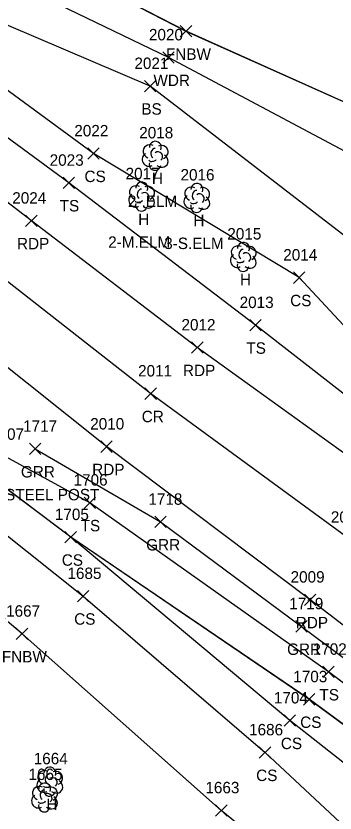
# Model space of a CAD drawing. Extents: x 1415642 to 1422021, y 544543 to 547232.
# Drawn here: x 1415966.4 to 1416022.2, y 546878.2 to 547017.8 of the extents above; entities that cross this region are included whole.
import ezdxf

# ---------------------------------------------------------------- set-up
doc = ezdxf.new("R2010")
doc.units = 0
for name, color, linetype in [('L_A', 7, 'Continuous'), ('L_C', 7, 'Continuous'), ('L_I', 7, 'Continuous'), ('L_TIC', 7, 'Continuous'), ('LAWA', 7, 'Continuous'), ('LELB', 7, 'Continuous'), ('LFNC', 7, 'Continuous'), ('LTD', 7, 'Continuous'), ('P_A', 7, 'Continuous'), ('P_I', 7, 'Continuous'), ('P_TIC', 7, 'Continuous'), ('PET', 7, 'Continuous'), ('PRC', 7, 'Continuous'), ('R_A', 7, 'Continuous'), ('R_C', 7, 'Continuous'), ('R_I', 7, 'Continuous'), ('R_TIC', 7, 'Continuous'), ('RGR', 7, 'Continuous')]:
    doc.layers.add(name, color=color, linetype=linetype)

msp = doc.modelspace()

# ---------------------------------------------------------------- linework, layer by layer
at = {"layer": 'L_TIC'}
for points in [[(1415995.11, 547014.1), (1415997.11, 547016.1)], [(1415997.11, 547014.1), (1415995.11, 547016.1)], [(1415992.05, 547009.51), (1415994.05, 547011.51)], [(1415994.05, 547009.51), (1415992.05, 547011.51)], [(1415988.85, 547004.5), (1415990.85, 547006.5)], [(1415990.85, 547004.5), (1415988.85, 547006.5)], [(1415978.91, 546992.7), (1415980.91, 546994.7)], [(1415980.91, 546992.7), (1415978.91, 546994.7)], [(1415974.6, 546987.56), (1415976.6, 546989.56)], [(1415976.6, 546987.56), (1415974.6, 546989.56)], [(1416014.88, 546970.97), (1416016.88, 546972.97)], [(1416016.88, 546970.97), (1416014.88, 546972.97)], [(1416007.25, 546962.65), (1416009.25, 546964.65)], [(1416009.25, 546962.65), (1416007.25, 546964.65)], [(1415978.27, 546931.57), (1415980.27, 546933.57)], [(1415980.27, 546931.57), (1415978.27, 546933.57)], [(1415974.94, 546925.54), (1415976.94, 546927.54)], [(1415976.94, 546925.54), (1415974.94, 546927.54)], [(1415974.94, 546925.54), (1415976.94, 546927.54)], [(1415976.94, 546925.54), (1415974.94, 546927.54)], [(1415977.11, 546915.22), (1415979.11, 546917.22)], [(1415979.11, 546915.22), (1415977.11, 546917.22)], [(1415966.43, 546908.62), (1415968.43, 546910.62)], [(1415968.43, 546908.62), (1415966.43, 546910.62)], [(1416020.03, 546901.96), (1416022.03, 546903.96)], [(1416022.03, 546901.96), (1416020.03, 546903.96)], [(1416016.63, 546897.15), (1416018.63, 546899.15)], [(1416018.63, 546897.15), (1416016.63, 546899.15)], [(1416013.25, 546893.44), (1416015.25, 546895.44)], [(1416015.25, 546893.44), (1416013.25, 546895.44)], [(1416008.92, 546887.85), (1416010.92, 546889.85)], [(1416010.92, 546887.85), (1416008.92, 546889.85)], [(1416001.28, 546877.71), (1416003.28, 546879.71)], [(1416003.28, 546877.71), (1416001.28, 546879.71)]]:
    msp.add_lwpolyline(points, dxfattribs=at)
at = {"layer": 'LAWA'}
for points in [[(1416240.56, 546960.73), (1416233.2, 546953.27), (1416224.51, 546941.93), (1416214.85, 546929.39), (1416199.95, 546923.14), (1416193.46, 546920.24), (1416179.13, 546920.7), (1416159.93, 546927.15), (1416126.32, 546945.38), (1416100.02, 546952.8), (1416028.43, 546991.66), (1415993.05, 547010.51), (1415954.88, 547028.97)], [(1416240.56, 546960.73), (1416233.2, 546953.27), (1416224.51, 546941.93), (1416214.86, 546929.39), (1416199.95, 546923.14), (1416193.46, 546920.24), (1416179.13, 546920.7), (1416159.93, 546927.15), (1416126.32, 546945.39), (1416100.02, 546952.81), (1416028.43, 546991.66), (1415993.05, 547010.51), (1415954.88, 547028.96)]]:
    msp.add_lwpolyline(points, dxfattribs=at)
at = {"layer": 'LELB'}
for points in [[(1416091.47, 546896.23), (1416067.28, 546915.33), (1416036.7, 546941.48), (1416008.25, 546963.65), (1415975.6, 546988.56), (1415942.26, 547013.09), (1415909.12, 547036.86), (1415872.92, 547061.56), (1415845.5, 547087.74), (1415809.03, 547112.5), (1415805.73, 547114.89), (1415787.7, 547125.97), (1415788.24, 547129.84), (1415790.68, 547131.85)], [(1416091.47, 546896.23), (1416067.28, 546915.33), (1416036.71, 546941.48), (1416008.26, 546963.65), (1415975.6, 546988.56), (1415942.26, 547013.09), (1415909.12, 547036.86), (1415872.92, 547061.56), (1415845.5, 547087.74), (1415809.04, 547112.5), (1415805.73, 547114.9), (1415787.7, 547125.97), (1415788.24, 547129.84), (1415790.68, 547131.85)], [(1416166.26, 546865.71), (1416159.51, 546874.18), (1416128.86, 546893.05), (1416099.94, 546911.95), (1416080.11, 546927.17), (1416051.61, 546951.27), (1416024.79, 546978.54), (1415989.85, 547005.5), (1415949.92, 547022.61), (1415918.77, 547047.8), (1415880.24, 547071.02), (1415848.8, 547092.4)], [(1416166.26, 546865.71), (1416159.51, 546874.18), (1416128.86, 546893.05), (1416099.95, 546911.94), (1416080.11, 546927.17), (1416051.61, 546951.27), (1416024.79, 546978.54), (1415989.85, 547005.5), (1415949.92, 547022.61), (1415918.78, 547047.8), (1415880.25, 547071.01), (1415848.8, 547092.4)], [(1416210.45, 546810.14), (1416187.24, 546828.5), (1416172.35, 546839.03), (1416162.91, 546845.64), (1416145.69, 546861.76), (1416125.16, 546875.54), (1416093.4, 546901.43), (1416075.19, 546919.9), (1416045.66, 546942.32), (1416039.77, 546946.29), (1416015.88, 546971.97), (1415979.91, 546993.7), (1415946.5, 547018.2), (1415914.22, 547042.27), (1415877.25, 547066.68), (1415845.5, 547087.74)], [(1416210.45, 546810.14), (1416187.24, 546828.5), (1416172.36, 546839.03), (1416162.91, 546845.64), (1416145.7, 546861.76), (1416125.16, 546875.54), (1416093.4, 546901.44), (1416075.18, 546919.9), (1416045.66, 546942.32), (1416039.77, 546946.29), (1416015.88, 546971.97), (1415979.91, 546993.7), (1415946.51, 547018.2), (1415914.22, 547042.27), (1415877.24, 547066.68), (1415845.5, 547087.74)], [(1416200.69, 546756.25), (1416177.76, 546767.63), (1416166.72, 546775.57), (1416158.94, 546780.74), (1416149.8, 546790.95), (1416145.27, 546792.19), (1416135.47, 546803.24), (1416119.09, 546819.38), (1416087.86, 546845.73), (1416058.66, 546867.92), (1416017.63, 546898.15), (1415975.94, 546926.54), (1415961.59, 546937.35), (1415930.25, 546967.22), (1415904.85, 546987.6), (1415883.27, 547005.7), (1415850.56, 547030.99), (1415821.69, 547055.02)], [(1416200.69, 546756.25), (1416177.77, 546767.63), (1416166.72, 546775.57), (1416158.93, 546780.74), (1416149.8, 546790.95), (1416145.28, 546792.19), (1416135.47, 546803.24), (1416119.09, 546819.38), (1416087.87, 546845.73), (1416058.67, 546867.92), (1416017.63, 546898.16), (1415975.95, 546926.55), (1415961.6, 546937.34), (1415930.25, 546967.22), (1415904.86, 546987.6), (1415883.28, 547005.7), (1415850.57, 547030.99), (1415821.7, 547055.02)], [(1415881.61, 546996.31), (1415913.06, 546969.47), (1415944.07, 546943.36), (1415978.11, 546916.22), (1416009.92, 546888.85), (1416034.36, 546866.02), (1416055.92, 546848.02), (1416074.4, 546832.78), (1416094.73, 546817.39), (1416113.97, 546812.22), (1416083.13, 546840.22), (1416056.24, 546861.43), (1416014.25, 546894.44), (1415975.94, 546926.54)], [(1415881.62, 546996.31), (1415913.07, 546969.47), (1415944.08, 546943.36), (1415978.12, 546916.23), (1416009.93, 546888.84), (1416034.36, 546866.03), (1416055.93, 546848.02), (1416074.4, 546832.78), (1416094.74, 546817.39), (1416113.98, 546812.22), (1416083.14, 546840.22), (1416056.24, 546861.43), (1416014.25, 546894.43), (1415975.95, 546926.55)], [(1416413.88, 546519.84), (1416385.73, 546558.12), (1416356.85, 546595.36), (1416336.82, 546621.39), (1416300.66, 546661.66), (1416278.22, 546684.25), (1416249.88, 546714.04), (1416230.93, 546728.9), (1416221.86, 546737.5), (1416200.69, 546756.25), (1416176.24, 546778.44), (1416157.26, 546793.38), (1416140.02, 546808.9), (1416121.84, 546825.58), (1416090.2, 546848.7), (1416061.67, 546872.28), (1416021.03, 546902.96), (1415979.27, 546932.57), (1415964.6, 546940.59)], [(1416413.88, 546519.84), (1416385.73, 546558.12), (1416356.85, 546595.36), (1416336.82, 546621.39), (1416300.66, 546661.66), (1416278.22, 546684.25), (1416249.88, 546714.04), (1416230.93, 546728.9), (1416221.87, 546737.51), (1416200.69, 546756.25), (1416176.24, 546778.44), (1416157.26, 546793.38), (1416140.03, 546808.9), (1416121.84, 546825.58), (1416090.21, 546848.7), (1416061.68, 546872.28), (1416021.04, 546902.96), (1415979.28, 546932.57), (1415964.61, 546940.59)]]:
    msp.add_lwpolyline(points, dxfattribs=at)
at = {"layer": 'LFNC'}
for points in [[(1416067.58, 546984.06), (1416031.2, 546999.34), (1415996.11, 547015.1), (1415957.45, 547035.03), (1415922.34, 547052.78), (1415883.85, 547076.17), (1415852.09, 547094.57), (1415823.18, 547113.63), (1415819.4, 547116.14), (1415815.46, 547118.48), (1415790.83, 547135.32)], [(1416067.58, 546984.06), (1416031.2, 546999.34), (1415996.12, 547015.09), (1415957.45, 547035.03), (1415922.34, 547052.78), (1415883.85, 547076.17), (1415852.09, 547094.57), (1415823.18, 547113.64), (1415819.41, 547116.14), (1415815.45, 547118.48), (1415790.83, 547135.32)], [(1416115.75, 546796.75), (1416105.56, 546801.9), (1416090.13, 546811.78), (1416082.81, 546817.76), (1416078.29, 546817.48), (1416069.09, 546824.45), (1416051.15, 546839.14), (1416026.27, 546859.13), (1416002.28, 546878.71), (1415967.43, 546909.62), (1415937.82, 546934.52), (1415909.35, 546961.09), (1415874.55, 546995.04)], [(1416115.75, 546796.75), (1416105.57, 546801.9), (1416090.14, 546811.78), (1416082.82, 546817.76), (1416078.29, 546817.48), (1416069.1, 546824.45), (1416051.16, 546839.14), (1416026.28, 546859.13), (1416002.28, 546878.71), (1415967.43, 546909.62), (1415937.83, 546934.51), (1415909.36, 546961.09), (1415874.56, 546995.04)]]:
    msp.add_lwpolyline(points, dxfattribs=at)
at = {"layer": 'LTD'}
for p, q in [((1415990.69, 546993.35), (1415990.69, 546993.35)), ((1415990.69, 546993.35), (1415990.69, 546993.35)), ((1415988.32, 546986.2), (1415988.32, 546986.2)), ((1415988.32, 546986.2), (1415988.32, 546986.2)), ((1415997.97, 546985.98), (1415997.97, 546985.98)), ((1415997.97, 546985.98), (1415997.97, 546985.98)), ((1416006.1, 546975.65), (1416006.1, 546975.65)), ((1416006.1, 546975.65), (1416006.1, 546975.65)), ((1415972.26, 546883.79), (1415972.26, 546883.79)), ((1415972.26, 546883.79), (1415972.26, 546883.79)), ((1415971.35, 546881.03), (1415971.35, 546881.03)), ((1415971.35, 546881.03), (1415971.35, 546881.03))]:
    msp.add_line(p, q, dxfattribs=at)
for centre in [(1415990.74, 546994.79), (1415988.36, 546987.64), (1415998.02, 546987.41), (1416006.14, 546977.09), (1415972.3, 546885.23), (1415971.39, 546882.46)]:
    msp.add_arc(centre, 1.05, 335.5272, 180.9563, dxfattribs=at)
for centre, major_axis, ratio, start_param, end_param in [((1415989.9, 546994.02), (1.21, -0.51), 0.895232, 1.570796, 4.712389), ((1415991.74, 546993.93), (-1.14, -0.48), 0.949671, 1.570796, 4.712389), ((1415990.49, 546993.81), (-0.208, -0.792), 0.645439, 3.141593, 6.283185), ((1415991.19, 546993.18), (-0.5, 0.667), 0.989748, 3.141593, 6.283185), ((1415989.61, 546992.64), (0.58, -1.04), 0.959034, 3.141593, 6.283185), ((1415990.24, 546992.6), (-0.625, -0.083), 0.423636, 0, 3.141593), ((1415991.69, 546992.52), (-1.09, 0.79), 0.841452, 1.570796, 4.712389), ((1415990.69, 546991.85), (0.26, 1.06), 0.942809, 1.570796, 4.712389), ((1415987.52, 546986.87), (1.21, -0.51), 0.895232, 1.570796, 4.712389), ((1415988.11, 546986.66), (-0.208, -0.792), 0.645439, 3.141593, 6.283185), ((1415988.82, 546986.04), (-0.5, 0.667), 0.989748, 3.141593, 6.283185), ((1415989.36, 546986.79), (-1.14, -0.48), 0.949671, 1.570796, 4.712389), ((1415997.18, 546986.64), (1.21, -0.51), 0.895232, 1.570796, 4.712389), ((1415997.76, 546986.43), (-0.208, -0.792), 0.645439, 3.141593, 6.283185), ((1415999.01, 546986.56), (-1.14, -0.48), 0.949671, 1.570796, 4.712389), ((1415987.23, 546985.5), (0.58, -1.04), 0.959034, 3.141593, 6.283185), ((1415987.86, 546985.45), (-0.625, -0.083), 0.423636, 0, 3.141593), ((1415989.32, 546985.37), (-1.09, 0.79), 0.841452, 1.570796, 4.712389), ((1415996.89, 546985.27), (0.58, -1.04), 0.959034, 3.141593, 6.283185), ((1415998.47, 546985.81), (-0.5, 0.667), 0.989748, 3.141593, 6.283185), ((1415998.97, 546985.14), (-1.09, 0.79), 0.841452, 1.570796, 4.712389), ((1415988.32, 546984.7), (0.26, 1.06), 0.942809, 1.570796, 4.712389), ((1415997.97, 546984.48), (0.26, 1.06), 0.942809, 1.570796, 4.712389), ((1415997.51, 546985.22), (-0.625, -0.083), 0.423636, 0, 3.141593), ((1416005.31, 546976.32), (1.21, -0.51), 0.895232, 1.570796, 4.712389), ((1416007.14, 546976.24), (-1.14, -0.48), 0.949671, 1.570796, 4.712389), ((1416005.01, 546974.94), (0.58, -1.04), 0.959034, 3.141593, 6.283185), ((1416005.89, 546976.11), (-0.208, -0.792), 0.645439, 3.141593, 6.283185), ((1416006.6, 546975.49), (-0.5, 0.667), 0.989748, 3.141593, 6.283185), ((1416007.1, 546974.82), (-1.09, 0.79), 0.841452, 1.570796, 4.712389), ((1416006.1, 546974.15), (0.26, 1.06), 0.942809, 1.570796, 4.712389), ((1416005.64, 546974.9), (-0.625, -0.083), 0.423636, 0, 3.141593), ((1415971.46, 546884.46), (1.21, -0.51), 0.895232, 1.570796, 4.712389), ((1415972.05, 546884.25), (-0.208, -0.792), 0.645439, 3.141593, 6.283185), ((1415973.3, 546884.37), (-1.14, -0.48), 0.949671, 1.570796, 4.712389), ((1415971.17, 546883.08), (0.58, -1.04), 0.959034, 3.141593, 6.283185), ((1415972.76, 546883.62), (-0.5, 0.667), 0.989748, 3.141593, 6.283185), ((1415973.26, 546882.96), (-1.09, 0.79), 0.841452, 1.570796, 4.712389), ((1415970.56, 546881.69), (1.21, -0.51), 0.895232, 1.570796, 4.712389), ((1415971.14, 546881.48), (-0.208, -0.792), 0.645439, 3.141593, 6.283185), ((1415972.26, 546882.29), (0.26, 1.06), 0.942809, 1.570796, 4.712389), ((1415971.8, 546883.04), (-0.625, -0.083), 0.423636, 0, 3.141593), ((1415972.39, 546881.61), (-1.14, -0.48), 0.949671, 1.570796, 4.712389), ((1415970.26, 546880.32), (0.58, -1.04), 0.959034, 3.141593, 6.283185), ((1415971.85, 546880.86), (-0.5, 0.667), 0.989748, 3.141593, 6.283185), ((1415972.35, 546880.19), (-1.09, 0.79), 0.841452, 1.570796, 4.712389), ((1415971.35, 546879.53), (0.26, 1.06), 0.942809, 1.570796, 4.712389), ((1415970.89, 546880.28), (-0.625, -0.083), 0.423636, 0, 3.141593)]:
    msp.add_ellipse(centre, major_axis=major_axis, ratio=ratio, start_param=start_param, end_param=end_param, dxfattribs=at)
at = {"layer": 'P_TIC'}
for points in [[(1415968.06, 546980.93), (1415970.06, 546982.93)], [(1415970.06, 546980.93), (1415968.06, 546982.93)], [(1415997.08, 546958.73), (1415999.08, 546960.73)], [(1415999.08, 546958.73), (1415997.08, 546960.73)], [(1415988.92, 546950.67), (1415990.92, 546952.67)], [(1415990.92, 546950.67), (1415988.92, 546952.67)], [(1415981.21, 546941.39), (1415983.21, 546943.39)], [(1415983.21, 546941.39), (1415981.21, 546943.39)], [(1416016.81, 546914.59), (1416018.81, 546916.59)], [(1416018.81, 546914.59), (1416016.81, 546916.59)]]:
    msp.add_lwpolyline(points, dxfattribs=at)
at = {"layer": 'PET'}
for points in [[(1416435.56, 546537.44), (1416408.53, 546574.61), (1416379.54, 546611.97), (1416358.62, 546637.86), (1416320.38, 546681.18), (1416299.04, 546704.62), (1416270.68, 546734.26), (1416256.1, 546749.21), (1416221.42, 546781.44), (1416197.8, 546803.68), (1416167.45, 546829.93), (1416146.9, 546847.39), (1416116.66, 546870.72), (1416088.42, 546892.72), (1416062.97, 546911.59), (1416031.6, 546935.61), (1415998.08, 546959.73), (1415969.06, 546981.93), (1415936.64, 547006.92)], [(1416435.56, 546537.44), (1416408.53, 546574.62), (1416379.54, 546611.97), (1416358.63, 546637.85), (1416320.38, 546681.18), (1416299.04, 546704.62), (1416270.69, 546734.26), (1416256.1, 546749.21), (1416221.42, 546781.44), (1416197.8, 546803.68), (1416167.45, 546829.93), (1416146.9, 546847.38), (1416116.66, 546870.72), (1416088.42, 546892.72), (1416062.98, 546911.58), (1416031.6, 546935.61), (1415998.08, 546959.73), (1415969.07, 546981.93), (1415936.65, 547006.92)], [(1416417.68, 546520.98), (1416388.9, 546560.28), (1416359.4, 546597.75), (1416339.06, 546622.92), (1416303.08, 546664.45), (1416282.37, 546687.64), (1416253.58, 546717.16), (1416237.44, 546733.28), (1416206.51, 546762.17), (1416181.86, 546784.67), (1416151.94, 546810.47), (1416130.39, 546828.26), (1416101.49, 546851.34), (1416072.78, 546874.03), (1416047.41, 546892.82), (1416017.81, 546915.59), (1415982.21, 546942.39), (1415954.4, 546964.56)], [(1416417.68, 546520.98), (1416388.9, 546560.28), (1416359.4, 546597.76), (1416339.06, 546622.93), (1416303.08, 546664.45), (1416282.37, 546687.65), (1416253.58, 546717.16), (1416237.44, 546733.28), (1416206.51, 546762.17), (1416181.87, 546784.67), (1416151.94, 546810.47), (1416130.39, 546828.26), (1416101.49, 546851.34), (1416072.78, 546874.03), (1416047.41, 546892.82), (1416017.81, 546915.59), (1415982.21, 546942.39), (1415954.4, 546964.56)]]:
    msp.add_lwpolyline(points, dxfattribs=at)
at = {"layer": 'PRC'}
for points in [[(1416425.29, 546532.23), (1416399.16, 546568.17), (1416370.34, 546605), (1416349.98, 546630.03), (1416312.55, 546673.44), (1416291.21, 546696.63), (1416262.58, 546725.99), (1416246.66, 546742.06), (1416214.68, 546772.43), (1416190.4, 546794.67), (1416160.38, 546819.82), (1416139.01, 546837.64), (1416109.6, 546860.71), (1416080.51, 546883.13), (1416051.44, 546902.01), (1416024.84, 546926.07), (1415989.92, 546951.67), (1415962.46, 546973.18)], [(1416425.29, 546532.24), (1416399.16, 546568.17), (1416370.35, 546605), (1416349.98, 546630.03), (1416312.55, 546673.45), (1416291.21, 546696.63), (1416262.58, 546725.99), (1416246.66, 546742.06), (1416214.67, 546772.43), (1416190.4, 546794.67), (1416160.38, 546819.82), (1416139.01, 546837.64), (1416109.6, 546860.71), (1416080.51, 546883.13), (1416051.45, 546902.01), (1416024.84, 546926.07), (1415989.92, 546951.68), (1415962.46, 546973.18)]]:
    msp.add_lwpolyline(points, dxfattribs=at)
at = {"layer": 'R_TIC'}
for points in [[(1415968.74, 546940.99), (1415970.74, 546942.99)], [(1415970.74, 546940.99), (1415968.74, 546942.99)], [(1415990.65, 546928.21), (1415992.65, 546930.21)], [(1415992.65, 546928.21), (1415990.65, 546930.21)], [(1416015.29, 546909.93), (1416017.29, 546911.93)], [(1416017.29, 546909.93), (1416015.29, 546911.93)]]:
    msp.add_lwpolyline(points, dxfattribs=at)
at = {"layer": 'RGR'}
for points in [[(1415969.74, 546941.99), (1415991.65, 546929.21), (1416016.29, 546910.93), (1416041.47, 546892.17), (1416068.82, 546871.25), (1416092.52, 546852.68), (1416119.85, 546831.08), (1416143.05, 546810.55), (1416160.13, 546797.47)], [(1415969.75, 546941.99), (1415991.65, 546929.21), (1416016.3, 546910.93), (1416041.48, 546892.18), (1416068.83, 546871.25), (1416092.52, 546852.68), (1416119.86, 546831.08), (1416143.05, 546810.55), (1416160.13, 546797.47)]]:
    msp.add_lwpolyline(points, dxfattribs=at)

# ---------------------------------------------------------------- texts
at = {"layer": 'L_A'}
for s, p in [('FNBW', (1415992.59, 547010.1)), ('WDR', (1415990.41, 547005.51)), ('BS', (1415988.29, 547000.5)), ('CS', (1415978.35, 546988.7)), ('H', (1415990.13, 546988.35)), ('TS', (1415974.01, 546983.56)), ('H', (1415987.75, 546981.2)), ('H', (1415997.4, 546980.98)), ('H', (1416005.53, 546970.65)), ('CS', (1416014.32, 546966.97)), ('TS', (1416006.66, 546958.65)), ('TS', (1415977.68, 546927.57)), ('CS', (1415974.38, 546921.54)), ('CS', (1415974.38, 546921.54)), ('CS', (1415976.55, 546911.22)), ('FNBW', (1415963.9, 546904.62)), ('TS', (1416019.44, 546897.96)), ('CS', (1416016.07, 546893.15)), ('CS', (1416012.69, 546889.44)), ('CS', (1416008.37, 546883.85)), ('H', (1415971.69, 546878.79))]:
    msp.add_text(s, height=2, dxfattribs=at).set_placement(p)
at = {"layer": 'L_C'}
for s, p in [('2-.ELM', (1415985.95, 546984.35)), ('2-M.ELM', (1415982.5, 546977.2)), ('3-S.ELM', (1415992.29, 546976.98))]:
    msp.add_text(s, height=2, dxfattribs=at).set_placement(p)
at = {"layer": 'L_I'}
for s, p in [('2020', (1415989.62, 547013.51)), ('2021', (1415987.08, 547008.5)), ('2022', (1415976.57, 546996.7)), ('2018', (1415987.92, 546996.35)), ('2023', (1415972.26, 546991.56)), ('2017', (1415985.54, 546989.2)), ('2016', (1415995.14, 546988.98)), ('2015', (1416003.33, 546978.65)), ('2014', (1416013.11, 546974.97)), ('2013', (1416005.48, 546966.65)), ('1707', (1415961.83, 546943.59)), ('1706', (1415976.44, 546935.57)), ('1705', (1415973.17, 546929.54)), ('1705', (1415973.17, 546929.54)), ('1685', (1415975.37, 546919.22)), ('1667', (1415964.64, 546912.62)), ('1702', (1416018.26, 546905.96)), ('1703', (1416014.86, 546901.15)), ('1704', (1416011.47, 546897.44)), ('1686', (1416007.13, 546891.85)), ('1664', (1415969.47, 546886.79)), ('1665', (1415968.56, 546884.03)), ('1663', (1415999.49, 546881.71))]:
    msp.add_text(s, height=2, dxfattribs=at).set_placement(p)
at = {"layer": 'P_A'}
for s, p in [('RDP', (1415966.55, 546976.93)), ('RDP', (1415995.57, 546954.73)), ('CR', (1415988.36, 546946.67)), ('RDP', (1415979.7, 546937.39)), ('RDP', (1416015.3, 546910.59))]:
    msp.add_text(s, height=2, dxfattribs=at).set_placement(p)
at = {"layer": 'P_I'}
for s, p in [('2024', (1415965.72, 546984.93)), ('2012', (1415995.31, 546962.73)), ('2011', (1415987.72, 546954.67)), ('2010', (1415979.35, 546945.39)), ('2008', (1416021.42, 546929.07)), ('2009', (1416014.39, 546918.59))]:
    msp.add_text(s, height=2, dxfattribs=at).set_placement(p)
at = {"layer": 'R_A'}
for p in [(1415967.23, 546936.99), (1415989.14, 546924.21), (1416013.78, 546905.93)]:
    msp.add_text('GRR', height=2, dxfattribs=at).set_placement(p)
at = {"layer": 'R_C'}
msp.add_text('SGR W/ STEEL POST', height=2, dxfattribs=at).set_placement((1415953.91, 546932.99))
at = {"layer": 'R_I'}
for s, p in [('1717', (1415967.61, 546944.99)), ('1718', (1415989.52, 546932.21)), ('1719', (1416014.16, 546913.93))]:
    msp.add_text(s, height=2, dxfattribs=at).set_placement(p)

doc.saveas('drawing.dxf')
